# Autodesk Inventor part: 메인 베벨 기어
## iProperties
Created: 2012-07
Part Number: 메인 베벨 기어
Material: Steel, Mild
Document SubType Name: Modeling
Designer: SeoGD™ [www.esajin.kr]
Categories: <?xml version="1.0" encoding="UTF-16"?> <MemberInstance><Categories><FamilyTemplate><FamilyTemplateParameter ValueType="xs:double" Id="1" ObjectReferenceKey="da
Mass: 289.975 g
Surface Area: 107.722 cm^2
Volume: 36.8925 cm^3
Density: 7.86 g/cm^3
CustomPartVersion: 1
Author: SeoGD™ [www.esajin.kr]
